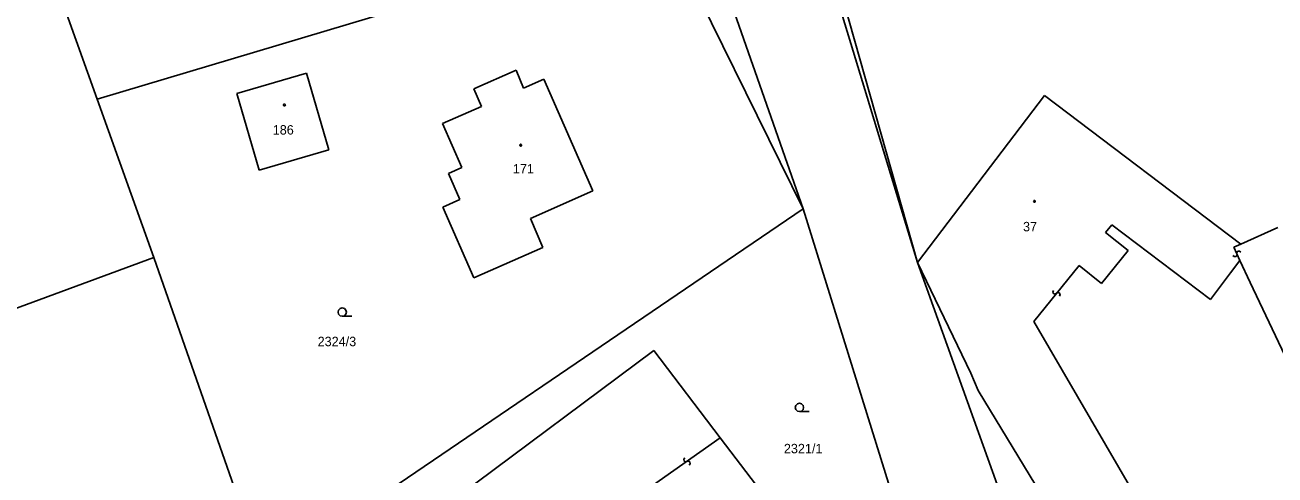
# Model space of a CAD drawing. Extents: x -747792 to -745414, y -1093712 to -1091463.
# Drawn here: x -746685.5 to -746572.8, y -1092891 to -1092850.4 of the extents above; entities that cross this region are included whole.
import ezdxf

# ---------------------------------------------------------------- set-up
doc = ezdxf.new("R2010")
doc.units = 0
for name, color, linetype in [('Pracovní_bod JDTM STC_VC', 7, 'Continuous'), ('Pracovní_bod JDTM STC_VC - výška', 7, 'Continuous'), ('Pracovní_bod JDTM STC_VC - číslo', 7, 'Continuous'), ('Pracovní_bod NN - výška', 7, 'Continuous'), ('Pracovní_bod polohopisu', 7, 'Continuous')]:
    doc.layers.add(name, color=color, linetype=linetype)

msp = doc.modelspace()

# ---------------------------------------------------------------- linework, layer by layer
at = {"layer": 'Pracovní_bod JDTM STC_VC - výška'}
for points in [[(-746662.13, -1092857.55), (-746662.08, -1092857.56), (-746662.05, -1092857.61), (-746662.04, -1092857.64), (-746662.05, -1092857.69), (-746662.09, -1092857.72), (-746662.13, -1092857.72), (-746662.18, -1092857.71), (-746662.21, -1092857.68), (-746662.22, -1092857.64), (-746662.21, -1092857.59), (-746662.17, -1092857.56)], [(-746640.81, -1092861.19), (-746640.76, -1092861.2), (-746640.74, -1092861.24), (-746640.73, -1092861.27), (-746640.74, -1092861.31), (-746640.78, -1092861.35), (-746640.81, -1092861.35), (-746640.85, -1092861.34), (-746640.89, -1092861.31), (-746640.9, -1092861.27), (-746640.89, -1092861.23), (-746640.84, -1092861.19)], [(-746594.47, -1092866.25), (-746594.42, -1092866.26), (-746594.4, -1092866.3), (-746594.39, -1092866.33), (-746594.4, -1092866.38), (-746594.44, -1092866.41), (-746594.47, -1092866.42), (-746594.51, -1092866.4), (-746594.54, -1092866.37), (-746594.55, -1092866.33), (-746594.54, -1092866.29), (-746594.5, -1092866.25)]]:
    msp.add_lwpolyline(points, close=True, dxfattribs=at)
at = {"layer": 'Pracovní_bod JDTM STC_VC - číslo'}
for points in [[(-746656.91, -1092876.7), (-746657.1, -1092876.65), (-746657.24, -1092876.51), (-746657.29, -1092876.32), (-746657.24, -1092876.14), (-746657.1, -1092876), (-746656.91, -1092875.95), (-746656.72, -1092876), (-746656.58, -1092876.14), (-746656.54, -1092876.32), (-746656.58, -1092876.51), (-746656.72, -1092876.65), (-746656.91, -1092876.7), (-746656.04, -1092876.7)], [(-746615.66, -1092885.3), (-746615.85, -1092885.25), (-746615.99, -1092885.11), (-746616.04, -1092884.93), (-746615.99, -1092884.74), (-746615.85, -1092884.6), (-746615.66, -1092884.55), (-746615.47, -1092884.6), (-746615.33, -1092884.74), (-746615.29, -1092884.93), (-746615.33, -1092885.11), (-746615.47, -1092885.25), (-746615.66, -1092885.3), (-746614.79, -1092885.3)]]:
    msp.add_lwpolyline(points, dxfattribs=at)
at = {"layer": 'Pracovní_bod NN - výška'}
for points in [[(-746688.21, -1092831.48), (-746679.02, -1092857.11)], [(-746605.01, -1092871.84), (-746616.4, -1092831.67)], [(-746624.42, -1092841.06), (-746615.33, -1092867)], [(-746679.02, -1092857.11), (-746627.76, -1092841.79)], [(-746615.33, -1092867), (-746627.76, -1092841.79)], [(-746613.27, -1092844.77), (-746605.01, -1092871.84)], [(-746645.05, -1092856.2), (-746641.22, -1092854.51)], [(-746641.22, -1092854.51), (-746640.56, -1092856.12)], [(-746666.42, -1092856.62), (-746660.14, -1092854.78)], [(-746660.14, -1092854.78), (-746658.12, -1092861.68)], [(-746640.56, -1092856.12), (-746638.72, -1092855.31)], [(-746638.72, -1092855.31), (-746634.31, -1092865.39)], [(-746664.4, -1092863.51), (-746666.42, -1092856.62)], [(-746644.36, -1092857.79), (-746645.05, -1092856.2)], [(-746593.57, -1092856.8), (-746605.01, -1092871.84)], [(-746575.86, -1092870.2), (-746593.57, -1092856.8)], [(-746679.02, -1092857.11), (-746673.9, -1092871.4)], [(-746647.86, -1092859.32), (-746644.36, -1092857.79)], [(-746646.12, -1092863.29), (-746647.86, -1092859.32)], [(-746658.12, -1092861.68), (-746664.4, -1092863.51)], [(-746647.33, -1092863.83), (-746646.12, -1092863.29)], [(-746646.3, -1092866.18), (-746647.33, -1092863.83)], [(-746634.31, -1092865.39), (-746639.94, -1092867.89)], [(-746663.9, -1092900.02), (-746615.33, -1092867)], [(-746647.85, -1092866.85), (-746646.3, -1092866.18)], [(-746645.04, -1092873.23), (-746647.85, -1092866.85)], [(-746615.33, -1092867), (-746604.26, -1092902.58)], [(-746639.94, -1092867.89), (-746638.81, -1092870.49)], [(-746575.86, -1092870.2), (-746572.52, -1092868.7)], [(-746702.19, -1092881.84), (-746673.9, -1092871.4)], [(-746673.9, -1092871.4), (-746663.9, -1092900.02)], [(-746638.81, -1092870.49), (-746645.04, -1092873.23)], [(-746605.01, -1092871.84), (-746600.2, -1092881.82)], [(-746605.01, -1092871.84), (-746593.18, -1092904.87)], [(-746628.81, -1092879.8), (-746646.38, -1092892.9)], [(-746622.81, -1092887.67), (-746628.81, -1092879.8)], [(-746600.2, -1092881.82), (-746599.54, -1092883.4)], [(-746588.72, -1092901.23), (-746599.54, -1092883.4)], [(-746622.81, -1092887.67), (-746608.35, -1092906.65)]]:
    msp.add_lwpolyline(points, dxfattribs=at)
at = {"layer": 'Pracovní_bod polohopisu'}
for points in [[(-746587.49, -1092868.45), (-746588.05, -1092869.15)], [(-746586.03, -1092870.78), (-746588.05, -1092869.15)], [(-746578.6, -1092875.18), (-746587.49, -1092868.45)], [(-746576.49, -1092870.48), (-746575.86, -1092870.2)], [(-746588.42, -1092873.74), (-746586.03, -1092870.78)], [(-746576.56, -1092871.21), (-746576.45, -1092871.32), (-746576.28, -1092871.31), (-746576.19, -1092871.19), (-746576.22, -1092870.94), (-746576.12, -1092870.82), (-746575.96, -1092870.82), (-746575.86, -1092870.93)], [(-746575.93, -1092871.66), (-746576.49, -1092870.48)], [(-746590.44, -1092872.11), (-746594.52, -1092877.17)], [(-746590.44, -1092872.11), (-746588.42, -1092873.74)], [(-746576.79, -1092872.79), (-746575.93, -1092871.66)], [(-746575, -1092873.65), (-746575.93, -1092871.66)], [(-746578.6, -1092875.18), (-746576.79, -1092872.79)], [(-746571.89, -1092880.25), (-746575, -1092873.65)], [(-746592.2, -1092874.89), (-746592.15, -1092874.75), (-746592.23, -1092874.6), (-746592.38, -1092874.57), (-746592.6, -1092874.71), (-746592.74, -1092874.66), (-746592.81, -1092874.52), (-746592.76, -1092874.39)], [(-746580.37, -1092901.51), (-746594.52, -1092877.17)], [(-746628.83, -1092891.92), (-746622.81, -1092887.67)], [(-746626.02, -1092889.47), (-746626.11, -1092889.6), (-746626.07, -1092889.76), (-746625.93, -1092889.83), (-746625.69, -1092889.76), (-746625.56, -1092889.84), (-746625.53, -1092890), (-746625.62, -1092890.12)]]:
    msp.add_lwpolyline(points, dxfattribs=at)

# ---------------------------------------------------------------- texts
at = {"layer": 'Pracovní_bod JDTM STC_VC'}
for s, p in [('186', (-746663.18, -1092860.31)), ('171', (-746641.52, -1092863.82)), ('37', (-746595.5, -1092869.04)), ('2324/3', (-746659.13, -1092879.4)), ('2321/1', (-746617.07, -1092889.06))]:
    msp.add_text(s, height=0.85, dxfattribs=at).set_placement(p)

doc.saveas('drawing.dxf')
